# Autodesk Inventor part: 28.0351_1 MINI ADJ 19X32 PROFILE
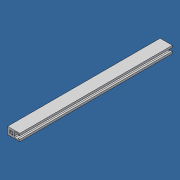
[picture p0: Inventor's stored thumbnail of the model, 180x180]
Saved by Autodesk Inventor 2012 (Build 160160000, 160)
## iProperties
Company: MiniTec Framing Systems, LLC
Created: 2013-07
Part Number: 28.0351_1 MINI ADJ 19X32 PROFILE
Material: Aluminum-6061
Description: PROFILE 19X32
Document SubType Name: Modeling
Designer: Admin
Stock Number: 20.1000 PROFILE 19X32
Density: 2.71 g/cm^3
FINISH: CLEAR ANODIZED
Author: Admin
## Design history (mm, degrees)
sketch "Sketch1"
  geometry: L1 (22.5, -4.1)-(18, -4.1) reference; L2 (18, -4.1)-(18, -6.8) reference; L3 (18, -6.8)-(9.5, -6.8) reference; L4 (9.5, -6.8)-(7.2, -4.5) reference; L5 (7.2, -4.5)-(7.2, 4.5) reference; L6 (7.2, 4.5)-(9.5, 6.8) reference; L7 (9.5, 6.8)-(18, 6.8) reference; L8 (18, 6.8)-(18, 4.1) reference; L9 (18, 4.1)-(22.5, 4.1) reference; L10 (-9.5, 9.5)-(22.5, 9.5) reference; L11 (-9.5, -9.5)-(-9.5, 9.5) reference; L12 (22.5, -9.5)-(-9.5, -9.5) reference; L13 (22.5, 9.5)-(22.5, 4.1) reference; L14 (22.5, -9.5)-(22.5, -4.1) reference; L15 (-3.263, 1.849)-(-4.596, 3.182) reference; L16 (-3.182, 4.596)-(-1.849, 3.263) reference; L17 (-4.596, 3.182)-(-3.182, 4.596) reference; L18 (1.849, 3.263)-(3.182, 4.596) reference; L19 (4.596, 3.182)-(3.263, 1.849) reference; L20 (3.182, 4.596)-(4.596, 3.182) reference; L21 (-4.596, -3.182)-(-3.263, -1.849) reference; L22 (-3.182, -4.596)-(-4.596, -3.182) reference; L23 (-1.849, -3.263)-(-3.182, -4.596) reference; L24 (3.182, -4.596)-(1.849, -3.263) reference; L25 (3.263, -1.849)-(4.596, -3.182) reference; L26 (4.596, -3.182)-(3.182, -4.596) reference; A1 r 3.75 centre (0, 0) between (-1.66, 3.362) and (-1.849, 3.263) reference; A2 r 3.75 centre (0, 0) between (1.849, 3.263) and (-1.66, 3.362) reference; A3 r 3.75 centre (0, 0) between (-3.263, 1.849) and (-3.263, -1.849) reference; A4 r 3.75 centre (0, 0) between (3.362, 1.66) and (3.263, 1.849) reference; A5 r 3.75 centre (0, 0) between (-1.849, -3.263) and (-1.66, -3.362) reference; A6 r 3.75 centre (0, 0) between (3.362, -1.66) and (3.362, 1.66) reference; A7 r 3.75 centre (0, 0) between (-1.66, -3.362) and (1.849, -3.263) reference; A8 r 3.75 centre (0, 0) between (3.263, -1.849) and (3.362, -1.66) reference
  constraints: 52 end point, 16 point on circle, 8 centre point, 6 horizontal, 5 vertical, 1 perpendicular, 61 other
extrude "Extrusion1" new body sketch "Sketch1" stored distance "d22" = 399.8; taper "d23" = 0 deg
thread "Thread5" dims "d32" = 25.4, "d33" = 0
thread "Thread6" dims "d34" = 25.4, "d35" = 0
thread "Thread7" dims "d36" = 25.4, "d37" = 0
thread "Thread8" dims "d38" = 25.4, "d39" = 0
body "Solid1"
